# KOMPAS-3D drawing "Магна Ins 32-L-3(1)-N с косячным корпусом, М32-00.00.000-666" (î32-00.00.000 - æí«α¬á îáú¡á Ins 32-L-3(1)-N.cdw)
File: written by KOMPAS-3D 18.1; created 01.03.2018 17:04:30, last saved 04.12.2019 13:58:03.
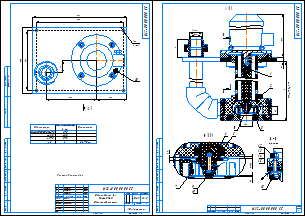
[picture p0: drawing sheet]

Sheets 1-2: A3, portrait

Document properties: Полное имя файла: C:\Users\Kon\Desktop\___М32-00.00.000  - Магна Ins 32-L-3(1)-N.spw; Масса: 40.608; Форматы листов документа: 2xA3

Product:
- Part/product: Магна Ins 32-L-3(1)-N с косячным корпусом  | designation М32-00.00.000-666
    Масса: 40.608
  - Component [detail]: Косячная (удолить)  | designation М40-00.00.007-6666  | pos. 118  | Масса: 8.81523; Раздел спецификации: Детали; Форматы листов документа: 3xA3; Примечание: @100~)3xA3; source file: ..\..\Магна ins 40\3Д\М40-00.00.007-01 - Заглушка.m3d, ..\Магна ins 40\3Д\М40-00.00.007-06 - Заглушка.cdw
  - Component [detail]: Защитная втулка  | designation М32-00.00.001  | pos. 6  | Раздел спецификации: Детали; Форматы листов документа: A4
  - Component [detail]: Втулка  | designation М32-00.00.002  | pos. 7  | Раздел спецификации: Детали; Форматы листов документа: A4
  - Component [detail]: Заглушка  | designation М32-00.00.007  | pos. 9  | Раздел спецификации: Детали; Форматы листов документа: A3
  - Component [assembly]: Корпус М32 с косячным корпусом М40  | designation М32-00.15.000-666  | pos. 1  | Масса: 9.75067; Раздел спецификации: Сборочные единицы; Форматы листов документа: A3; Примечание: См. заказ; source file: ..\М32-00.15.000 - Корпус М32.a3d
  - Component [assembly]: Вал  | designation М32-00.10.000  | pos. 2  | Масса: 1.67698; Раздел спецификации: Сборочные единицы; Форматы листов документа: A3; Примечание: См. заказ
  - Component [detail]: Кольцо 120-125-30 EPDM / ГОСТ 9833-73  | pos. 18  | Раздел спецификации: Прочие изделия
  - Component [detail]: Заглушка @2~32 FV PPR ф. "FV-Plast"  | qty 3  | pos. 19  | Материал: Полипропилен  ГОСТ 26996-86 (density 900 kg/m3); Масса: 0.0281994; Раздел спецификации: Прочие изделия
  - Component [detail]: Заглушка  | designation М32-00.00.007М32  | pos. 9  | Раздел спецификации: Детали; Форматы листов документа: A3; source file: ..\..\Магна ins 40\3Д\М40-00.00.007-01 - Заглушка.m3d, М32-00.00.007 - Заглушка.cdw
  - Component [detail]: Втулка / скольжения  | designation М11-00.00.002  | pos. 70  | Масса: 0.026501; Раздел спецификации: Детали; Форматы листов документа: A4
  - Component [detail]: Защитная втулка  | designation М11-00.00.003  | pos. 71  | Масса: 0.0186143; Раздел спецификации: Детали; Форматы листов документа: A4; source file: ..\..\Магна ins 11\Магна N\3Д\Магна INS 11\М11-00.00.003 - Защитная втулка.m3d, ..\..\Магна ins 11\Магна N\3Д\Магна INS 11\Чертежи\М11-00.00.003 - Защитная втулка.cdw
- Part/product: Сборка Магна Ins 32-L-3(1)-N  | designation М32-00.00.000
    Масса: 40.608
    source file: М32-00.00.000 СБ - Магна Ins 32-L-3(1)-N.cdw
  - Component [detail]: Втулка скольжения  | designation М11-00.00.002  | pos. 70  | Масса: 0.026501; Раздел спецификации: Детали; Форматы листов документа: A4; source file: М11-00.00.002 - Втулка скольжения.m3d, Чертежи\М11-00.00.002 - Втулка скольжения.cdw
  - Component [detail]: Защитная втулка  | designation М11-00.00.003  | pos. 71  | Масса: 0.0186143; Раздел спецификации: Детали; Форматы листов документа: A4; source file: М11-00.00.003 - Защитная втулка.m3d, Чертежи\М11-00.00.003 - Защитная втулка.cdw
  - Component [detail]: Заглушка  | designation М32-00.00.007М32  | pos. 9  | Масса: 8.94851; Раздел спецификации: Детали; Форматы листов документа: A3; source file: ..\М32-00.00.007 - Заглушка.cdw, М40-00.00.007-01 - Заглушка.m3d
  - Component [detail]: Колпачок М10  | designation М40-00.00.009  | pos. 10  | Масса: 0.0397944; Раздел спецификации: Детали; Форматы листов документа: A3; source file: \\192.168.87.28\Konstructor_doc\Магна\Магна Ins\Магна ins 40\3Д\М40-00.00.009 - Колпачок М10.cdw, М40-00.00.009 - Колпачок М10.m3d
  - Component [detail]: Кольцо уплотнительное плоское 10-18-25 ЕPDM  | pos. 20  | Масса: 0.000562973; Раздел спецификации: Прочие изделия; source file: Кольцо уплотнительное плоское 10-18-25 ЕPDM.m3d
  - Component [detail]: Заглушка 32 FV PPR ф. "FV-Plast"  | qty 3  | pos. 19  | Материал: Полипропилен  ГОСТ 26996-86 (density 900 kg/m3); Масса: 0.0281994; Раздел спецификации: Прочие изделия; source file: ..\..\..\..\1 ПКИ 3D\Полипропиленовые фитинги, трубы\Заглушка ф32 FV PPR ф. FV-Plast.m3d
  - Component [detail]: Заглушка 32 FV PPR ф. "FV-Plast"  | qty 4  | pos. 19  | Материал: Полипропилен  ГОСТ 26996-86 (density 900 kg/m3); Масса: 0.0281994; Раздел спецификации: Прочие изделия; source file: Заглушка ф32 FV PPR ф. FV-Plast.m3d
  - Component [assembly]: Узел Вал  | designation М32-00.10.000  | pos. 2  | Масса: 1.67698; Раздел спецификации: Сборочные единицы; Форматы листов документа: A3; Примечание: См. заказ; source file: C:\Users\User\Desktop\Вал _ М32-00.10.000.spw, М32-00.10.000 - Вал.cdw, М32-00.10.000 - Узел Вал.a3d
  - Component [assembly]: Узел Корпус М32  | designation М32-00.15.000  | pos. 1  | Масса: 9.83678; Раздел спецификации: Сборочные единицы; Форматы листов документа: A3; Примечание: См. заказ; source file: М32-00.15.000 - Корпус М32.cdw, М32-00.15.000 - Узел Корпус М32.a3d
  - Component [standard]: Гайка М14-6H.21.12Х18Н10Т ГОСТ 5915-70  | qty 4  | pos. 13
      Материал: Сталь 12Х18Н10Т ГОСТ 5632-72 (density 1000 kg/m3)
      Масса: 0.02891
      Раздел спецификации: Стандартные изделия
      Примечание: нерж.
      additional columns: Сталь 12Х18Н10Т ГОСТ 5632-72
      source file: C:\Program Files\ASCON\KOMPAS-3D v18\Libs\PartLib\DATA\VAULT\methods\kompas\3d\PLib_Nut_OST92_900.m3d
  - Component [standard]: Болт М14-6gx80.21.12Х18Н10Т ГОСТ 7805-70  | qty 3  | Материал: Сталь 12Х18Н10Т ГОСТ 5632-72 (density 1000 kg/m3); Масса: 0.1221; Раздел спецификации: Стандартные изделия; source file: C:\Program Files\ASCON\KOMPAS-3D v18\Libs\PartLib\DATA\VAULT\methods\kompas\3d\PLib_Bolt_1_900.m3d
  - Component [standard]: Шайба 14 30Х13 019 ГОСТ 6402-70  | qty 3  | Материал: Сталь 30Х13 ГОСТ 5632-72 (density 1000 kg/m3); Масса: 0.00448; Раздел спецификации: Стандартные изделия; source file: C:\Program Files\ASCON\KOMPAS-3D v18\Libs\PartLib\DATA\VAULT\methods\kompas\3d\PLib_Washer_2_712.m3d
  - Component [standard]: Шайба C.14.21 ГОСТ 11371-78  | qty 4  | pos. 15  | Материал: Сталь 12Х18Н10Т ГОСТ 5632-72 (density 1000 kg/m3); Масса: 0.008377; Раздел спецификации: Стандартные изделия; additional columns: Сталь 12Х18Н10Т ГОСТ 5632-72; source file: C:\Program Files\ASCON\KOMPAS-3D v18\Libs\PartLib\DATA\VAULT\methods\kompas\3d\PLib_Washer_1_712.m3d
  - Component [standard]: Шайба C.14.21 ГОСТ 11371-78  | qty 4  | pos. 15
      Материал: Сталь 12Х18Н10Т ГОСТ 5632-72 (density 1000 kg/m3)
      Масса: 0.008377
      Раздел спецификации: Стандартные изделия
      Примечание: нерж.
      additional columns: Сталь 12Х18Н10Т ГОСТ 5632-72
      source file: C:\Program Files\ASCON\KOMPAS-3D v18\Libs\PartLib\DATA\VAULT\methods\kompas\3d\PLib_Washer_1_712.m3d
  - Component [detail]: Электродвигатель 90L2 380В 3кВт 3000об/мин 3081 / арт.: DRV090-L2-003-0-3030 DRIVE IEK  | pos. 21  | Масса: 19; Раздел спецификации: Прочие изделия; source file: Электродвигатель 90L2 380В 3кВт 3000об_мин 3081 DRIVE IEK.m3d
  - Component [detail]: Рабочее колесо М32  | designation М32-00.00.003  | pos. 8  | Масса: 0.258528; Раздел спецификации: Детали; Форматы листов документа: A3; source file: М32-00.00.003 - Рабочее колесо М32.m3d
  - Component [standard]: Шайба C.14.21 ГОСТ 11371-78  | pos. 3  | Масса: 0.0084; Раздел спецификации: Стандартные изделия; Примечание: нерж.; additional columns: Сталь 12Х18Н10Т ГОСТ 5632-72; source file: C:\Program Files\ASCON\KOMPAS-3D v18\Libs\PartLib\DATA\VAULT\methods\kompas\3d\PLib_Washer_1_712.m3d
  - Component [standard]: Шайба C.14.21 ГОСТ 11371-78  | qty 3  | pos. 15  | Материал: Сталь 12Х18Н10Т ГОСТ 5632-72; Масса: 0.0084; Раздел спецификации: Стандартные изделия; additional columns: Сталь 12Х18Н10Т ГОСТ 5632-72; source file: C:\Program Files\ASCON\KOMPAS-3D v18\Libs\PartLib\DATA\VAULT\methods\kompas\3d\PLib_Washer_1_712.m3d
  - Component [standard]: Шайба 14 30Х13 019 ГОСТ 6402-70  | qty 3  | pos. 120  | Материал: Сталь 30Х13 ГОСТ 5632-72; Масса: 0.0045; Раздел спецификации: Стандартные изделия; source file: C:\Program Files\ASCON\KOMPAS-3D v18\Libs\PartLib\DATA\VAULT\methods\kompas\3d\PLib_Washer_2_712.m3d
  - Component [standard]: Гайка М14-6H.21.12Х18Н10Т ГОСТ 5915-70  | qty 3  | pos. 13
      Материал: Сталь 12Х18Н10Т ГОСТ 5632-72
      Масса: 0.0289
      Раздел спецификации: Стандартные изделия
      Примечание: нерж.
      additional columns: Сталь 12Х18Н10Т ГОСТ 5632-72
      source file: C:\Program Files\ASCON\KOMPAS-3D v18\Libs\PartLib\DATA\VAULT\methods\kompas\3d\PLib_Nut_OST92_900.m3d
  - Component [standard]: Болт М14-6gx80.21.12Х18Н10Т ГОСТ 7805-70  | qty 3  | pos. 119  | Материал: Сталь 12Х18Н10Т ГОСТ 5632-72; Масса: 0.1221; Раздел спецификации: Стандартные изделия; source file: C:\Program Files\ASCON\KOMPAS-3D v18\Libs\PartLib\DATA\VAULT\methods\kompas\3d\PLib_Bolt_1_900.m3d
  - Component [standard]: Шайба C.14.21 ГОСТ 11371-78  | qty 2  | pos. 15
      Материал: Сталь 12Х18Н10Т ГОСТ 5632-72
      Масса: 0.0084
      Раздел спецификации: Стандартные изделия
      Примечание: нерж.
      additional columns: Сталь 12Х18Н10Т ГОСТ 5632-72
      source file: C:\Program Files\ASCON\KOMPAS-3D v18\Libs\PartLib\DATA\VAULT\methods\kompas\3d\PLib_Washer_1_712.m3d

Title block, sheet 1: Наименование: Сборка Магна Ins / 32-L-3(1)-N / Сборочный чертеж; Масса: 40,61; scale: 1:2,5; sheet number: 1; Количество листов документа: 2; organisation: АО «Астерион»; Форматы листов документа: A3; stored path: \\192.168.87.28\Konstructor_doc\Магна\Магна Ins\Магна ins 32\М32-00.00.000 - Магна Ins 32-L-3(1)-N.cdw; Разработал: Милов; Т. контр.: Лучихин
Title block, sheet 2: Наименование: Магна Ins / 32-L-3(1)-N / Сборочный чертеж; Масса: 40,63; sheet number: 2

Views: Вид по стрелке 2, Местный разрез 1, Местный разрез 2, Выносной элемент 3, Разрез В-В, Вид по стрелке А, Вид:1, Вид:2, Вид:3
Referenced files in D:\Magna\Магна Ins\Магна ins 32\Для Караби\: М32-00.00.000 - Сборка Магна Ins 32-L-3(1)-N.a3d, М32-00.15.000 - Узел Корпус М32.a3d, М32-00.15.000 - Корпус М32.cdw, М32-00.10.000 - Узел Вал.a3d, М32-00.10.000 - Вал.cdw, М32-00.00.003 - Рабочее колесо М32.m3d, Заглушка ф32 FV PPR ф. FV-Plast.m3d, М40-00.00.009 - Колпачок М10.m3d, М40-00.00.007-01 - Заглушка.m3d, Электродвигатель 90L2 380В 3кВт 3000об_мин 3081 DRIVE IEK.m3d, Кольцо уплотнительное плоское 10-18-25 ЕPDM.m3d, М11-00.00.002 - Втулка скольжения.m3d, М11-00.00.003 - Защитная втулка.m3d, М32-00.15.001 - Фланец.m3d, М32-00.20.000 - Узел Корпус.a3d, М32-00.21.000 - Узел Кольцо.a3d, М32-00.21.001 - Кольцо.m3d, М32-00.20.002 - Корпус.m3d, М40-00.30.001 - Штифт 10.m3d, М32-00.22.001 - Колонна.m3d, Труба 63 PN10 S=5,8 FV PPR ф. FV PLAST.m3d, Колено 45гр 63 FV PPR ф. FV PLAST.m3d, М32-00.15.002 - Основание.m3d, Фланец МР ф63 РР.m3d, Фланец прижимной МР ф63 РР.m3d, Гайка МР ф63 РР.m3d, Муфта разборная ф63 РР.a3d, М32-00.10.001 - Вал.m3d, М40-00.10.002 - Фиксатор.m3d
Referenced files in Z:\Магна\Магна Ins\Магна ins 32\: М32-00.00.000 - Магна Ins 32-L-3(1)-N.a3d, М32-00.00.001 - Защитная втулка.m3d, М32-00.10.002 - Фиксатор.m3d, М32-00.00.007 - Заглушка.m3d, М32-00.22.002 - Отбойник.m3d, М32-00.00.004 - Шайба.m3d, М32-00.00.003 - Рабочее колесо М32.m3d, М32-00.20.003 - Крышка.m3d, М32-00.00.005 - Колпачек.m3d, М32-00.20.002 - Корпус.m3d, М32-00.10.003 - Отбойник.m3d, М32-00.20.001 - Стопор.m3d, М32-00.10.001 - Вал.m3d, М32-00.00.002 -  Втулка.m3d
Referenced files in C:\Users\User\Desktop\: Вал _ М32-00.10.000.spw
Referenced files in \\192.168.87.28\Konstructor_doc\Магна\Магна Ins\Магна ins 40\3Д\: М40-00.00.009 - Колпачок М10.cdw
Referenced files in D:\Magna\Магна Ins\Магна ins 32\Для Караби\..\: М32-00.00.007 - Заглушка.cdw
Referenced files in D:\1 ПКИ 3D\Полипропиленовые фитинги, трубы\: Заглушка ф32 FV PPR ф. FV-Plast.m3d
Referenced files in D:\Magna\Магна Ins\Магна ins 32\Для Караби\Чертежи\: М11-00.00.002 - Втулка скольжения.cdw, М11-00.00.003 - Защитная втулка.cdw
Referenced files in D:\Magna\Магна Ins\Магна ins 32\: М32-00.00.000  - Магна Ins 32-L-3(1)-N.spw, М32-00.20.002 - Корпус.m3d
Referenced files in C:\Program Files\ASCON\KOMPAS-3D v18\Libs\PartLib\DATA\VAULT\methods\kompas\3d\: PLib_Bolt_1_900.m3d, PLib_Washer_1_712.m3d, PLib_Nut_OST92_900.m3d, PLib_Washer_2_712.m3d, PLib_Screw_GOST_11074-84_900.m3d, PLib_Screw_GOST_8878-84_900.m3d, PLib_Blind_Nut_type1_900.m3d
Referenced files in D:\1 ПКИ 3D\Полипропиленовые фитинги, трубы\Трубы\: Труба 63 PN10 S=5,8 FV PPR ф. FV PLAST.m3d
Referenced files in C:\Program Files\ASCON\KOMPAS-3D V16\Libs\PartLib\DATA\VAULT\Methods\kompas\3d\: PLib_Nut_OST92_900.m3d, PLib_Screw_GOST_8878-84_900.m3d, PLib_Screw_GOST_11074-84_900.m3d, PLib_Washer_1_712.m3d, PLib_Washer_2_712.m3d, PLib_Bolt_1_900.m3d
Referenced files in C:\Program Files\ASCON\KOMPAS-3D V16\Libs\PartLib\DATA\vault\Methods\Kompas\3D\: PLib_Nut_OST92_900.m3d, PLib_Screw_GOST_8878-84_900.m3d, PLib_Washer_1_712.m3d, PLib_Blind_Nut_type1_900.m3d
Referenced files in D:\Отработать\Магна 40\3Д\: Электродвигатель 90L2 380В 3кВт 3000об_мин 3081 DRIVE IEK.m3d
Referenced files in D:\3Д модели\Кольца\: Кольцо 012-016-25 EPDM ГОСТ 9833-76.m3d
Referenced files in Z:\1 ПКИ 3D\РТИ\Кольца ГОСТ 9833-76\: Кольцо 022-025-19 EPDM ГОСТ 9833-76.m3d, Кольцо 120-125-30 EPDM ГОСТ 9833-73.m3d
Referenced files in Z:\1 ПКИ 3D\Полипропиленовые фитинги, трубы\Разборные муфты\: Фланец прижимной МР ф63 РР.m3d, Гайка МР ф63 РР.m3d, Фланец МР ф63 РР.m3d
Referenced files in Z:\1 ПКИ 3D\Полипропиленовые фитинги, трубы\Трубы\: Труба 63 PN10 S=5,8 FV PPR ф. FV PLAST.m3d
Referenced files in Z:\1 ПКИ 3D\Полипропиленовые фитинги, трубы\: Заглушка ф32 FV PPR ф. FV-Plast.m3d
Referenced files in \\192.168.87.28\Konstructor_doc\Магна\Магна Ins\Магна ins 32\: М32-00.21.001 - Кольцо.m3d
Referenced files in Z:\Магна\Магна Ins\Магна ins 40\3Д\Проработка\3Д\: Электродвигатель 90L2 380В 3кВт 3000об_мин 3081 DRIVE IEK.m3d
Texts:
  Длина погружной части
  L, мм
  L 475 мм
  min
  Гайка М14-6H.21.12Х18Н10Т ГОСТ 5915-70
  Гайка
  ГОСТ
  нерж.
  Узел Корпус М32
  См. заказ
  Шайба C.14.21 ГОСТ 11371-78
  Шайба
  Узел Вал
  Рабочее колесо М32
  Заглушка 32 FV PPR ф. "FV-Plast"
  Колпачок М10
  Заглушка
  Заглушка  32 FV PPR ф. "FV-Plast"
  Заглушка @2~32 FV PPR ф. "FV-Plast"
  Электродвигатель 90L2 380В 3кВт 3000об/мин 3081
  арт.: DRV090-L2-003-0-3030 DRIVE IEK
  Электродвигатель 90L2 380В 3кВт 3000об/мин 3081 / арт.: DRV090-L2-003-0-3030 DRIVE IEK
  Кольцо уплотнительное плоское
  Кольцо уплотнительное плоское / 10-18-25 ЕPDM
  Шайба 14 30Х13 019 ГОСТ 6402-70
  3D_Doc-graphic.lyt,1.000000-4294967295-182860482931
  Втулка
  скольжения
  Втулка / скольжения
  Защитная втулка
  Болт М14-6gx80.21.12Х18Н10Т ГОСТ 7805-70
  Болт
  Лифлянд
  Фланец
  Кольцо
  Труба 63 PN10 S=5,8 FV PPR ф. FV PLAST
  Узел Кольцо
  Корпус
  Штифт 10
  Узел Корпус
  Колонна
  Колено 45 63 FV PPR ф. "FV PLAST"
  Основание
  Фланец МР ф63 РР
  Фланец прижимной МР ф63 РР
  Гайка МР ф63 РР
  Муфта разборная ф63 РР
  Вал
  Винт A.М10-6gx30.21.12Х18Н10Т ГОСТ 11074-93
  Винт A.М8-6gx20.21.12Х18Н10Т ГОСТ 8878-93
  Фиксатор
  Кольцо уплотнительное плоское 10-18-25 ЕPDM
  Гайка М10-6H.21.12Х18Н10Т ГОСТ 11860-85
  Шайба C.8.21 ГОСТ 11371-78
  Втулка скольжения
  Сборка Магна Ins 32-L-3(1)-N
  Главный
Dimensions and other numbers on the sheet: 475; -425; -375; 425; 375; 51,4; 61,8; 87; 307; 375 _ 425 _ 475; 58; 1; 2; 8; 20; 39; 1,5; 3; 6; 5; 7; 9; 19; 4,5; 4 места; 18; 12; 13; 14; 15; 4; 21; 12Х18Н10Т; 019; 40Х; 10-18-25 ЕPDM; 30Х13; 0; 1:2,5; 32-L-3(1)-N; 40,61; 01.07.2019; 12.07.2019; 22.08.2019; 40,63; 02

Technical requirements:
  Размеры для справок.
